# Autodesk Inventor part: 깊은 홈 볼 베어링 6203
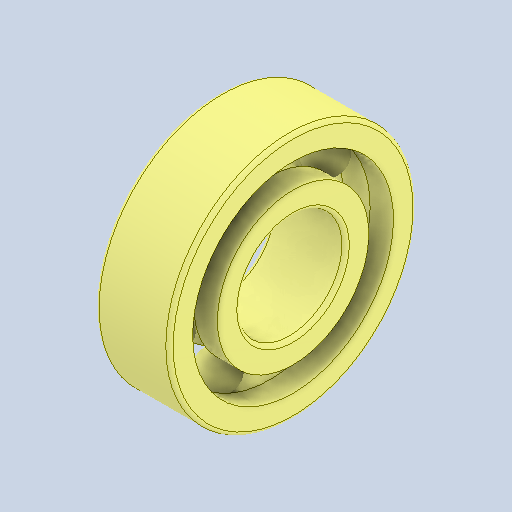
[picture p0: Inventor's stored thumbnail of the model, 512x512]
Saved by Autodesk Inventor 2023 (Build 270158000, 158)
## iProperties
Created: 2025-04
Part Number: 깊은 홈 볼 베어링 6203
Material: 강철, 연강
Description: 깊은 그루브 볼 베어링
Document SubType Name: Modeling
Designer: Admin
Density: 7.86 g/cm^3
Appearance: 기본값
Author: jhkim
Revision Number: 1
Sending System: Autodesk Inventor 2026
Preprocessor: ST-DEVELOPER v20.1
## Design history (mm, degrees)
feature "Solid1"
feature "Solid1:1"
feature "Solid1:2"
feature "Solid1:3"
feature "Solid1:4"
feature "Solid1:5"
feature "Solid1:6"
feature "Solid1:7"
feature "Solid1:8"
node "솔리드1"
node "솔리드2"
node "솔리드3"
node "솔리드4"
node "솔리드5"
node "솔리드6"
node "솔리드7"
node "솔리드8"
node "솔리드9"
